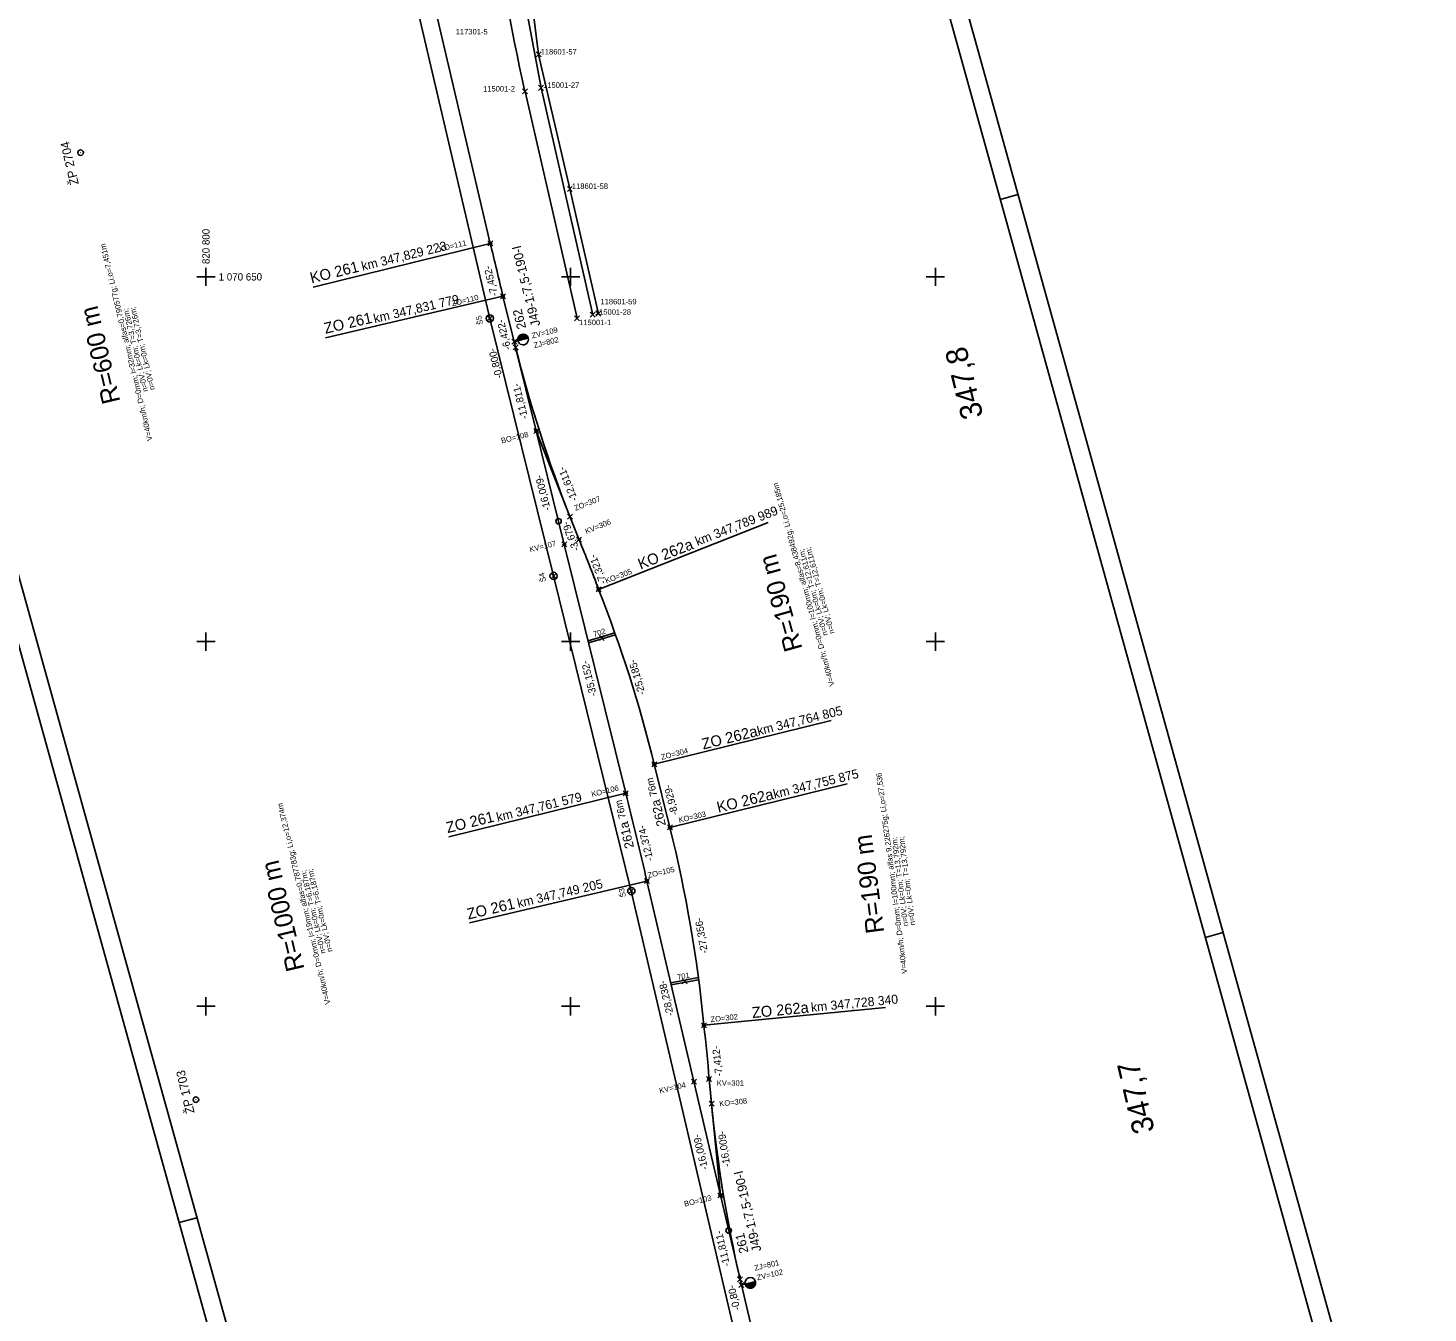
# Model space of a CAD drawing. Extents: x -821029 to -820632, y -1070881 to -1069931.
# Drawn here: x -820824.4 to -820632.5, y -1070792 to -1070615.9 of the extents above; entities that cross this region are included whole.
import ezdxf

# ---------------------------------------------------------------- set-up
doc = ezdxf.new("R2010")
doc.units = 0
for name, color, linetype in [('Ram', 7, 'Continuous'), ('Sit', 7, 'Continuous'), ('SO-11-10-01', 7, 'Continuous'), ('SO-11-50-01', 7, 'Continuous'), ('SO-11-86-01', 7, 'Continuous'), ('Sttaniceni a namezniky', 7, 'Continuous'), ('VB_SO-11-10-01', 7, 'Continuous'), ('VB_SO-11-50-01', 7, 'Continuous'), ('VB_SO-11-73-01', 7, 'Continuous'), ('VB_SO-11-86-01', 7, 'Continuous'), ('ZBP', 7, 'Continuous')]:
    doc.layers.add(name, color=color, linetype=linetype)

msp = doc.modelspace()

# ---------------------------------------------------------------- linework, layer by layer
at = {"layer": 'Ram'}
for p, q in [((-820688.68, -1070638.72), (-820691.09, -1070639.39)), ((-820660.57, -1070739.89), (-820662.98, -1070740.56)), ((-820801.24, -1070778.98), (-820803.65, -1070779.65))]:
    msp.add_line(p, q, dxfattribs=at)
for points in [[(-820857.35, -1070031.72), (-820632.46, -1070841.06), (-820775.54, -1070880.81), (-821000.43, -1070071.48)], [(-820859.09, -1070034.8), (-820635.54, -1070839.32), (-820773.8, -1070877.73), (-820997.35, -1070073.22)]]:
    msp.add_lwpolyline(points, dxfattribs=at)
at = {"layer": 'Sit'}
for p, q in [((-820800, -1070648.75), (-820800, -1070650)), ((-820750, -1070648.75), (-820750, -1070650)), ((-820700, -1070648.75), (-820700, -1070650)), ((-820801.25, -1070650), (-820800, -1070650)), ((-820798.75, -1070650), (-820800, -1070650)), ((-820800, -1070651.25), (-820800, -1070650)), ((-820751.25, -1070650), (-820750, -1070650)), ((-820748.75, -1070650), (-820750, -1070650)), ((-820750, -1070651.25), (-820750, -1070650)), ((-820701.25, -1070650), (-820700, -1070650)), ((-820698.75, -1070650), (-820700, -1070650)), ((-820700, -1070651.25), (-820700, -1070650)), ((-820800, -1070698.75), (-820800, -1070700)), ((-820750, -1070698.75), (-820750, -1070700)), ((-820700, -1070698.75), (-820700, -1070700)), ((-820801.25, -1070700), (-820800, -1070700)), ((-820798.75, -1070700), (-820800, -1070700)), ((-820800, -1070701.25), (-820800, -1070700)), ((-820751.25, -1070700), (-820750, -1070700)), ((-820748.75, -1070700), (-820750, -1070700)), ((-820750, -1070701.25), (-820750, -1070700)), ((-820701.25, -1070700), (-820700, -1070700)), ((-820698.75, -1070700), (-820700, -1070700)), ((-820700, -1070701.25), (-820700, -1070700)), ((-820801.25, -1070750), (-820800, -1070750)), ((-820800, -1070748.75), (-820800, -1070750)), ((-820798.75, -1070750), (-820800, -1070750)), ((-820800, -1070751.25), (-820800, -1070750)), ((-820751.25, -1070750), (-820750, -1070750)), ((-820750, -1070748.75), (-820750, -1070750)), ((-820748.75, -1070750), (-820750, -1070750)), ((-820750, -1070751.25), (-820750, -1070750)), ((-820701.25, -1070750), (-820700, -1070750)), ((-820700, -1070748.75), (-820700, -1070750)), ((-820698.75, -1070750), (-820700, -1070750)), ((-820700, -1070751.25), (-820700, -1070750))]:
    msp.add_line(p, q, dxfattribs=at)
at = {"layer": 'SO-11-10-01'}
for p, q in [((-820785.29, -1070651.4), (-820761.02, -1070645.41)), ((-820783.62, -1070658.36), (-820759.28, -1070652.66)), ((-820757.73, -1070658.89), (-820759.28, -1070652.66)), ((-820757.23, -1070658.77), (-820755.81, -1070658.41)), ((-820757.22, -1070658.38), (-820756.77, -1070658.65)), ((-820757.14, -1070658.2), (-820756.51, -1070658.59)), ((-820757.02, -1070658.05), (-820756.24, -1070658.52)), ((-820756.85, -1070657.93), (-820755.98, -1070658.46)), ((-820756.6, -1070657.86), (-820755.84, -1070658.32)), ((-820757.23, -1070658.77), (-820757.73, -1070658.89)), ((-820757.25, -1070658.58), (-820757.03, -1070658.71)), ((-820722.9, -1070683.69), (-820746.17, -1070692.84)), ((-820751.11, -1070686.73), (-820750.63, -1070686.61)), ((-820742.44, -1070720.8), (-820750.87, -1070686.67)), ((-820749.08, -1070686.12), (-820748.62, -1070685.94)), ((-820747.6, -1070699.9), (-820743.94, -1070698.81)), ((-820747.53, -1070700.19), (-820743.84, -1070699.09)), ((-820745.72, -1070699.49), (-820745.72, -1070699.49)), ((-820714.26, -1070710.82), (-820738.53, -1070716.82)), ((-820736.38, -1070725.49), (-820738.53, -1070716.82)), ((-820712.11, -1070719.49), (-820736.38, -1070725.49)), ((-820766.71, -1070726.78), (-820742.44, -1070720.8)), ((-820763.88, -1070738.54), (-820739.54, -1070732.83)), ((-820733.1, -1070760.32), (-820739.54, -1070732.83)), ((-820736.28, -1070746.77), (-820732.49, -1070746.07)), ((-820736.21, -1070747.06), (-820732.45, -1070746.37)), ((-820734.35, -1070746.57), (-820734.35, -1070746.57)), ((-820706.85, -1070750.17), (-820731.73, -1070752.6)), ((-820731.26, -1070760), (-820730.76, -1070759.96)), ((-820729.46, -1070775.91), (-820731.01, -1070759.98)), ((-820733.35, -1070760.38), (-820732.86, -1070760.27)), ((-820726.08, -1070788.07), (-820726.58, -1070788.19)), ((-820714.71, -1070838.92), (-820726.58, -1070788.19)), ((-820724.66, -1070787.74), (-820726.08, -1070788.07)), ((-820726.07, -1070788.13), (-820725.26, -1070788.63)), ((-820725.88, -1070788.02), (-820725.03, -1070788.55)), ((-820725.62, -1070787.96), (-820724.86, -1070788.43)), ((-820725.36, -1070787.9), (-820724.75, -1070788.29)), ((-820725.1, -1070787.84), (-820724.67, -1070788.11)), ((-820724.84, -1070787.78), (-820724.64, -1070787.91))]:
    msp.add_line(p, q, dxfattribs=at)
for points in [[(-820761.02, -1070645.41), (-820786.89, -1070534.87), (-820787.46, -1070532.43), (-820788.03, -1070530), (-820808.6, -1070442.09), (-820809.13, -1070439.8), (-820809.67, -1070437.51), (-820820.71, -1070390.32)], [(-820717.05, -1070839.46), (-820726.3, -1070799.93), (-820741.68, -1070734.2), (-820752.33, -1070691), (-820761.08, -1070655.69), (-820772.47, -1070607.01), (-820783.86, -1070558.32), (-820795.25, -1070509.64), (-820806.65, -1070460.95), (-820811.32, -1070440.97)], [(-820750.87, -1070686.67), (-820754.71, -1070671.13), (-820757.54, -1070659.67), (-820757.73, -1070658.89)], [(-820750.87, -1070686.67), (-820754.71, -1070671.13), (-820757.73, -1070658.89)], [(-820757.3, -1070660.1), (-820757.54, -1070659.67), (-820757.55, -1070660.17)], [(-820748.85, -1070686.03), (-820750.09, -1070682.87), (-820754.71, -1070671.13)], [(-820748.85, -1070686.03), (-820750.09, -1070682.87), (-820754.71, -1070671.13)], [(-820729.46, -1070775.91), (-820730.68, -1070763.36), (-820731.01, -1070759.98)], [(-820726.58, -1070788.19), (-820726.77, -1070787.41), (-820729.46, -1070775.91), (-820733.1, -1070760.32)], [(-820726.58, -1070788.19), (-820729.46, -1070775.91), (-820733.1, -1070760.32)], [(-820727, -1070786.97), (-820726.77, -1070787.41), (-820726.75, -1070786.91)]]:
    msp.add_lwpolyline(points, dxfattribs=at)
for centre, radius in [((-820761.02, -1070645.41), 0.2), ((-820759.28, -1070652.66), 0.2), ((-820761.08, -1070655.69), 0.5), ((-820754.71, -1070671.13), 0.2), ((-820752.33, -1070691), 0.5), ((-820746.17, -1070692.84), 0.2), ((-820738.53, -1070716.82), 0.2), ((-820742.44, -1070720.8), 0.2), ((-820736.38, -1070725.49), 0.2), ((-820739.54, -1070732.83), 0.2), ((-820741.68, -1070734.2), 0.5), ((-820731.73, -1070752.6), 0.2), ((-820729.46, -1070775.91), 0.2), ((-820725.37, -1070787.91), 0.732)]:
    msp.add_circle(centre, radius, dxfattribs=at)
for centre, start, end in [((-820756.52, -1070658.59), 13.8982, 193.8591), ((-820756.52, -1070658.59), 193.6439, 14.1134), ((-820725.37, -1070787.91), 193.1913, 13.1522)]:
    msp.add_arc(centre, 0.732, start, end, dxfattribs=at)
for centre, major_axis, ratio, start_param, end_param in [((-821297.45, -1070778.88), (-137, 584.15), 0.921302, 4.712391, 4.724811), ((-820573.45, -1070613.37), (68.39, -177.27), 0.999052, 4.590716, 4.719059), ((-820924.28, -1070758.98), (55, 181.87), 0.999992, 5.361609, 5.400139), ((-820922.85, -1070762.38), (-45.59, 184.45), 0.999308, 4.712395, 4.844949), ((-821629.82, -1070941.66), (-228.37, 973.58), 0.914441, 4.712392, 4.724766), ((-820920.82, -1070771.08), (3.93, 189.96), 0.999915, 4.830454, 4.97538), ((-820920.38, -1070774.75), (1, 190), 0.999687, 4.795486, 4.834494), ((-820542.45, -1070745), (25.65, -188.26), 0.995413, 4.674375, 4.802717)]:
    msp.add_ellipse(centre, major_axis=major_axis, ratio=ratio, start_param=start_param, end_param=end_param, dxfattribs=at)
at = {"layer": 'SO-11-50-01'}
msp.add_line((-820756.25, -1070624.59), (-820749.11, -1070655.68), dxfattribs=at)
msp.add_lwpolyline([(-820760.35, -1070555.8), (-820760.28, -1070567.75), (-820757.36, -1070577.72), (-820756.23, -1070594.45), (-820757.69, -1070604.64), (-820754.06, -1070624.09), (-820746.96, -1070655.19)], dxfattribs=at)
msp.add_arc((-820512.52, -1070568.97), 250, 180.3346, 192.8532, dxfattribs=at)
at = {"layer": 'SO-11-86-01'}
msp.add_lwpolyline([(-820756.73, -1070600.68), (-820754.4, -1070619.51), (-820750.11, -1070637.94), (-820746.2, -1070655.06)], dxfattribs=at)
at = {"layer": 'Sttaniceni a namezniky'}
for centre in [(-820751.65, -1070683.5), (-820728.33, -1070780.74)]:
    msp.add_circle(centre, 0.375, dxfattribs=at)
at = {"layer": 'VB_SO-11-10-01'}
for p, q in [((-820761.36, -1070645.76), (-820760.67, -1070645.07)), ((-820760.67, -1070645.76), (-820761.36, -1070645.07)), ((-820759.62, -1070653), (-820758.93, -1070652.31)), ((-820758.93, -1070653), (-820759.62, -1070652.31)), ((-820761.42, -1070656.04), (-820760.73, -1070655.35)), ((-820760.73, -1070656.04), (-820761.42, -1070655.35)), ((-820758.08, -1070659.23), (-820757.39, -1070658.55)), ((-820757.39, -1070659.23), (-820758.08, -1070658.55)), ((-820758.08, -1070659.23), (-820757.39, -1070658.55)), ((-820757.39, -1070659.23), (-820758.08, -1070658.55)), ((-820757.89, -1070660.01), (-820757.2, -1070659.32)), ((-820757.2, -1070660.01), (-820757.89, -1070659.32)), ((-820755.05, -1070671.48), (-820754.37, -1070670.79)), ((-820754.37, -1070671.48), (-820755.05, -1070670.79)), ((-820750.44, -1070683.21), (-820749.75, -1070682.52)), ((-820749.75, -1070683.21), (-820750.44, -1070682.52)), ((-820751.21, -1070687.02), (-820750.52, -1070686.33)), ((-820750.52, -1070687.02), (-820751.21, -1070686.33)), ((-820749.19, -1070686.37), (-820748.5, -1070685.69)), ((-820748.5, -1070686.37), (-820749.19, -1070685.69)), ((-820752.67, -1070691.34), (-820751.99, -1070690.65)), ((-820751.99, -1070691.34), (-820752.67, -1070690.65)), ((-820746.51, -1070693.19), (-820745.82, -1070692.5)), ((-820745.82, -1070693.19), (-820746.51, -1070692.5)), ((-820746.06, -1070699.84), (-820745.38, -1070699.15)), ((-820745.38, -1070699.84), (-820746.06, -1070699.15)), ((-820738.87, -1070717.16), (-820738.18, -1070716.48)), ((-820738.18, -1070717.16), (-820738.87, -1070716.48)), ((-820742.78, -1070721.14), (-820742.09, -1070720.46)), ((-820742.09, -1070721.14), (-820742.78, -1070720.46)), ((-820736.73, -1070725.83), (-820736.04, -1070725.14)), ((-820736.04, -1070725.83), (-820736.73, -1070725.14)), ((-820739.88, -1070733.17), (-820739.2, -1070732.49)), ((-820739.2, -1070733.17), (-820739.88, -1070732.49)), ((-820742.03, -1070734.55), (-820741.34, -1070733.86)), ((-820741.34, -1070734.55), (-820742.03, -1070733.86)), ((-820734.69, -1070746.91), (-820734.01, -1070746.22)), ((-820734.01, -1070746.91), (-820734.69, -1070746.22)), ((-820732.08, -1070752.95), (-820731.39, -1070752.26)), ((-820731.39, -1070752.95), (-820732.08, -1070752.26)), ((-820733.45, -1070760.67), (-820732.76, -1070759.98)), ((-820732.76, -1070760.67), (-820733.45, -1070759.98)), ((-820731.36, -1070760.32), (-820730.67, -1070759.64)), ((-820730.67, -1070760.32), (-820731.36, -1070759.64)), ((-820731.03, -1070763.71), (-820730.34, -1070763.02)), ((-820730.34, -1070763.71), (-820731.03, -1070763.02)), ((-820729.8, -1070776.26), (-820729.11, -1070775.57)), ((-820729.11, -1070776.26), (-820729.8, -1070775.57)), ((-820727.11, -1070787.76), (-820726.42, -1070787.07)), ((-820726.42, -1070787.76), (-820727.11, -1070787.07)), ((-820726.93, -1070788.54), (-820726.24, -1070787.85)), ((-820726.24, -1070788.54), (-820726.93, -1070787.85)), ((-820726.93, -1070788.54), (-820726.24, -1070787.85)), ((-820726.24, -1070788.54), (-820726.93, -1070787.85))]:
    msp.add_line(p, q, dxfattribs=at)
at = {"layer": 'VB_SO-11-50-01'}
for p, q in [((-820754.4, -1070624.43), (-820753.72, -1070623.74)), ((-820753.72, -1070624.43), (-820754.4, -1070623.74)), ((-820756.6, -1070624.93), (-820755.91, -1070624.24)), ((-820755.91, -1070624.93), (-820756.6, -1070624.24)), ((-820749.45, -1070656.03), (-820748.77, -1070655.34)), ((-820748.77, -1070656.03), (-820749.45, -1070655.34)), ((-820747.31, -1070655.54), (-820746.62, -1070654.85)), ((-820746.62, -1070655.54), (-820747.31, -1070654.85))]:
    msp.add_line(p, q, dxfattribs=at)
at = {"layer": 'VB_SO-11-86-01'}
for p, q in [((-820754.74, -1070619.85), (-820754.06, -1070619.16)), ((-820754.06, -1070619.85), (-820754.74, -1070619.16)), ((-820750.45, -1070638.28), (-820749.77, -1070637.59)), ((-820749.77, -1070638.28), (-820750.45, -1070637.59)), ((-820746.54, -1070655.41), (-820745.86, -1070654.72)), ((-820745.86, -1070655.41), (-820746.54, -1070654.72))]:
    msp.add_line(p, q, dxfattribs=at)
at = {"layer": 'ZBP'}
for p, q in [((-820817.17, -1070633), (-820817.18, -1070632.95)), ((-820801.36, -1070762.82), (-820801.37, -1070762.77))]:
    msp.add_line(p, q, dxfattribs=at)
for centre in [(-820817.18, -1070632.97), (-820801.37, -1070762.8)]:
    msp.add_circle(centre, 0.378, dxfattribs=at)

# ---------------------------------------------------------------- texts
at = {"layer": 'Sit'}
msp.add_text('820 800', height=1, rotation=90, dxfattribs=at).set_placement((-820799.5, -1070648.25))
msp.add_text('1 070 650', height=1, dxfattribs=at).set_placement((-820798.25, -1070650.5))
at = {"layer": 'SO-11-10-01'}
for s, height, rotation, p in [('V=40km/h; D=0mm; l=32mm; alfas=0,790577g; Li,o=7,451m', 0.75, 103.5041, (-820807.31, -1070672.38)), ('km 347,829 223', 1.25, 13.8549, (-820778.51, -1070649.17)), ('J49-1:7,5-190-I', 1.25, 103.8787, (-820754.15, -1070656.61)), ('KO 261 ', 1.5, 13.8549, (-820785.52, -1070650.9)), ('-7,452-', 1, 103.5041, (-820759.97, -1070652.53)), ('km 347,831 779', 1.25, 13.1993, (-820776.86, -1070656.35)), ('R=600 m', 2.5, 103.5041, (-820811.72, -1070667.08)), ('n=0V; Lk=0m; T=3,726m;', 0.75, 103.5041, (-820806.98, -1070665.43)), ('262', 1.25, 103.8787, (-820756.08, -1070657)), ('n=0V; Lk=0m; T=3,726m;', 0.75, 103.5041, (-820807.93, -1070665.66)), ('ZO 261 ', 1.5, 13.1993, (-820783.61, -1070657.81)), ('-6,422-', 1, 103.8848, (-820758.15, -1070659.89)), ('-0,800-', 1, 103.8787, (-820759.32, -1070663.8)), ('-11,811-', 1, 103.8787, (-820755.84, -1070669.35)), ('-16,009-', 1, 103.8826, (-820752.73, -1070681.91)), ('-12,611-', 1, 111.4808, (-820749.01, -1070680.55)), ('V=40km/h; D=0mm; l=100mm; alfas=8,438492g; Li,o=25,185m', 0.75, 105.6473, (-820713.8, -1070706)), ('km 347,789 989', 1.25, 21.4745, (-820732.61, -1070686.9)), ('-3,679-', 1, 111.4758, (-820748.76, -1070687.37)), ('KO 262a ', 1.5, 21.4745, (-820740.41, -1070690.14)), ('-7,321-', 1, 110.9599, (-820745.06, -1070691.91)), ('R=190 m', 2.5, 105.6473, (-820718.2, -1070700.96)), ('n=0V; Lk=0m; T=12,611m;', 0.75, 105.6473, (-820714.73, -1070699.08)), ('n=0V; Lk=0m; T=12,611m;', 0.75, 105.6473, (-820713.8, -1070698.82)), ('-25,185-', 1, 105.6473, (-820739.76, -1070707.15)), ('-35,152-', 1, 103.8825, (-820746.41, -1070707.38)), ('km 347,764 805', 1.25, 13.885, (-820724.26, -1070712.88)), ('ZO 262a ', 1.5, 13.885, (-820731.82, -1070714.81)), ('km 347,755 875', 1.25, 13.8823, (-820722.05, -1070721.54)), ('76m', 1, 103.8806, (-820738.1, -1070721.09)), ('-8,929-', 1, 103.8806, (-820735.26, -1070723.67)), ('V=40km/h; D=0mm; l=100mm; alfas 9,226275g; Li,o=27,536', 0.75, 97.3426, (-820703.84, -1070745.47)), ('km 347,761 579', 1.25, 13.8494, (-820760, -1070724.71)), ('76m', 1, 103.7596, (-820742.38, -1070724.15)), ('262a', 1.25, 103.8806, (-820736.92, -1070725.16)), ('KO 262a ', 1.5, 13.8823, (-820729.75, -1070723.48)), ('V=40km/h; D=0mm; l=19mm; alfas=0,787783g; Li,o=12,374m', 0.75, 103.4354, (-820782.92, -1070749.64)), ('ZO 261 ', 1.5, 13.8494, (-820766.87, -1070726.27)), ('261a', 1.25, 103.4354, (-820741.3, -1070728.2)), ('-12,374-', 1, 103.4354, (-820738.66, -1070729.96)), ('R=190 m', 2.5, 97.3426, (-820707, -1070739.86)), ('n=0V; Lk=0m; T=13,792m;', 0.75, 97.3426, (-820703.7, -1070738.97)), ('n=0V; Lk=0m; T=13,792m;', 0.75, 97.3426, (-820702.74, -1070738.85)), ('R=1000 m', 2.5, 103.4354, (-820786.48, -1070744.88)), ('n=0V; Lk=0m; T=6,187m;', 0.75, 103.4354, (-820783.58, -1070742.69)), ('n=0V; Lk=0m; T=6,187m;', 0.75, 103.4354, (-820782.64, -1070742.47)), ('km 347,749 205', 1.25, 13.2011, (-820757.16, -1070736.5)), ('ZO 261 ', 1.5, 13.2011, (-820764.03, -1070738.11)), ('-27,356-', 1, 99.6938, (-820731.17, -1070742.7)), ('-28,238-', 1, 103.1745, (-820735.85, -1070751.22)), ('km 347,728 340', 1.25, 5.5793, (-820716.99, -1070750.77)), ('ZO 262a ', 1.5, 5.5793, (-820725.07, -1070751.62)), ('-7,412-', 1, 96.1629, (-820729.17, -1070759.59)), ('-16,009-', 1, 103.1717, (-820731.15, -1070772.3)), ('-16,009-', 1, 98.5176, (-820728.11, -1070771.94)), ('J49-1:7,5-190-I', 1.25, 103.1734, (-820723.85, -1070783.48)), ('-11,811-', 1, 103.1734, (-820728.14, -1070785.53)), ('261', 1.25, 103.1722, (-820725.61, -1070783.7)), ('-0,80-', 1, 103.1734, (-820726.74, -1070791.54))]:
    msp.add_text(s, height=height, rotation=rotation, dxfattribs=at).set_placement(p)
at = {"layer": 'Sttaniceni a namezniky'}
for s, rotation, p in [('347,8', 103.8826, (-820693.41, -1070669.1)), ('347,7', 103.1734, (-820669.91, -1070767.07))]:
    msp.add_text(s, height=3, rotation=rotation, dxfattribs=at).set_placement(p)
at = {"layer": 'VB_SO-11-10-01'}
for s, rotation, p in [('KO=111', 13.1701, (-820767.93, -1070646.54)), ('ZO=110', 13.8848, (-820766.22, -1070654.04)), ('Š5', 103.8848, (-820761.98, -1070656.46)), ('ZV=109', 13.8787, (-820755.25, -1070658.45)), ('ZJ=802', 13.8787, (-820754.96, -1070659.77)), ('BO=108', 13.8826, (-820759.44, -1070672.84)), ('ZO=307', 21.4758, (-820749.34, -1070682.09)), ('KV=306', 22.0637, (-820747.84, -1070685.27)), ('KV=107', 13.8825, (-820755.54, -1070687.76)), ('Š4', 103.8825, (-820753.35, -1070691.73)), ('KO=305', 21.2044, (-820745.09, -1070692.06)), ('702', 16.5837, (-820746.79, -1070699.38)), ('ZO=304', 14.4724, (-820737.49, -1070716.22)), ('KO=106', 13.7596, (-820747.06, -1070721.31)), ('KO=303', 13.2206, (-820735.11, -1070724.85)), ('ZO=105', 13.1745, (-820739.35, -1070732.42)), ('Š3', 103.1745, (-820742.41, -1070734.97)), ('701', 10.416, (-820735.33, -1070746.37)), ('ZO=302', 6.1629, (-820730.78, -1070752.18)), ('KV=104', 13.1745, (-820737.76, -1070761.95)), ('KO=308', 6.1629, (-820729.58, -1070763.73)), ('BO=103', 13.1734, (-820734.35, -1070777.47)), ('ZJ=801', 13.1722, (-820724.72, -1070786.26)), ('ZV=102', 13.1722, (-820724.39, -1070787.58))]:
    msp.add_text(s, height=0.75, rotation=rotation, dxfattribs=at).set_placement(p)
msp.add_text('KV=301', height=0.75, dxfattribs=at).set_placement((-820729.96, -1070760.89))
at = {"layer": 'VB_SO-11-50-01'}
for s, p in [(' 115001-2', (-820762.29, -1070624.59)), (' 115001-27', (-820754.06, -1070624.09)), (' 115001-28', (-820746.96, -1070655.19)), (' 115001-1', (-820749.11, -1070656.62))]:
    msp.add_text(s, height=0.75, dxfattribs=at).set_placement(p)
at = {"layer": 'VB_SO-11-73-01'}
msp.add_text(' 117301-5', height=0.75, dxfattribs=at).set_placement((-820766.04, -1070616.76))
at = {"layer": 'VB_SO-11-86-01'}
for s, p in [(' 118601-57', (-820754.4, -1070619.51)), (' 118601-58', (-820750.11, -1070637.94)), (' 118601-59', (-820746.2, -1070653.77))]:
    msp.add_text(s, height=0.75, dxfattribs=at).set_placement(p)
at = {"layer": 'ZBP'}
for s, rotation, p in [('ŽP 2704', 103.1705, (-820817.42, -1070637.26)), ('ŽP 1703', 103.1745, (-820801.55, -1070764.57))]:
    msp.add_text(s, height=1.2, rotation=rotation, dxfattribs=at).set_placement(p)

doc.saveas('drawing.dxf')
